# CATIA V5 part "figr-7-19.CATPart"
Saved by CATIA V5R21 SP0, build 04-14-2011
Part number: Part2
Bounding box of the stored display mesh (mm): x -50 to 50, y -65 to 65, z 0 to 28
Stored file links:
  D:\CATIA V5R21 E-RESOURCES\CATIA-V5R21\catia-v5r21-prt\c07-catia-v5r20-prt\c07-catia-v5r21-figr-7-19.CATPart
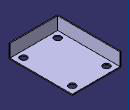
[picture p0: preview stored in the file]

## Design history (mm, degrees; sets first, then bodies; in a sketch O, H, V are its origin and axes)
Body1 (main body)
  Sketch1 on xy-plane, origin (0, 0, 0), H (1, 0, 0), V (0, 1, 0)
    line L1 (-50, 65) -> (50, 65)
    line L2 (50, 65) -> (50, -65)
    line L3 (50, -65) -> (-50, -65)
    line L4 (-50, -65) -> (-50, 65)
    axis line L5 (50, -65) -> (-50, 65)
    length L3 = 100
    length L2 = 130
    horizontal: L1 H, L3 H
    vertical: L2 V, L4 V
    midpoint: O L5
  Pad1: profile Sketch1, direction (0, 0, 1), length 28
  Shell1: ExtOffset 0, Face (face of Pad1; face of Pad1; face of Pad1), IntOffset 2
  Sketch2 on face of Pad1, origin (25.9302, -33.7092, 28), H (1, 0, 0), V (0, 1, 0)
    point P1 (9.0698, -16.2908)
    reference projected line E1 (-75.9302, -31.2908) -> (24.0698, -31.2908) from edge [face of Pad1 | face of Pad1]
    reference projected line E2 (24.0698, -31.2908) -> (24.0698, 98.7092) from edge [face of Pad1 | face of Pad1]
    distance P1 E1 = 15
    distance P1 E2 = 15
  Hole1: placed by Sketch2, at (35, -50, 28) direction (0, 0, -1), diameter 14, through (limit type 3)
  RectPattern1: of Hole1, direction 1 instances 2, spacing 100, along edge [face of Pad1 | face of Pad1], direction 2 instances 2, spacing 70, along edge [face of Pad1 | face of Pad1]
